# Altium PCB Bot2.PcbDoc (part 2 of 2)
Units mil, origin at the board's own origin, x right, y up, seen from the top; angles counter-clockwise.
Board outline 1717.4 x 2323.5 mil, 2 copper layers (Top1, Bottom2), stack 14.611 mil thick; 246 components, 15 nets, 1108 pads, 443 vias.
Unrouted connection lines stored in the file: 11.
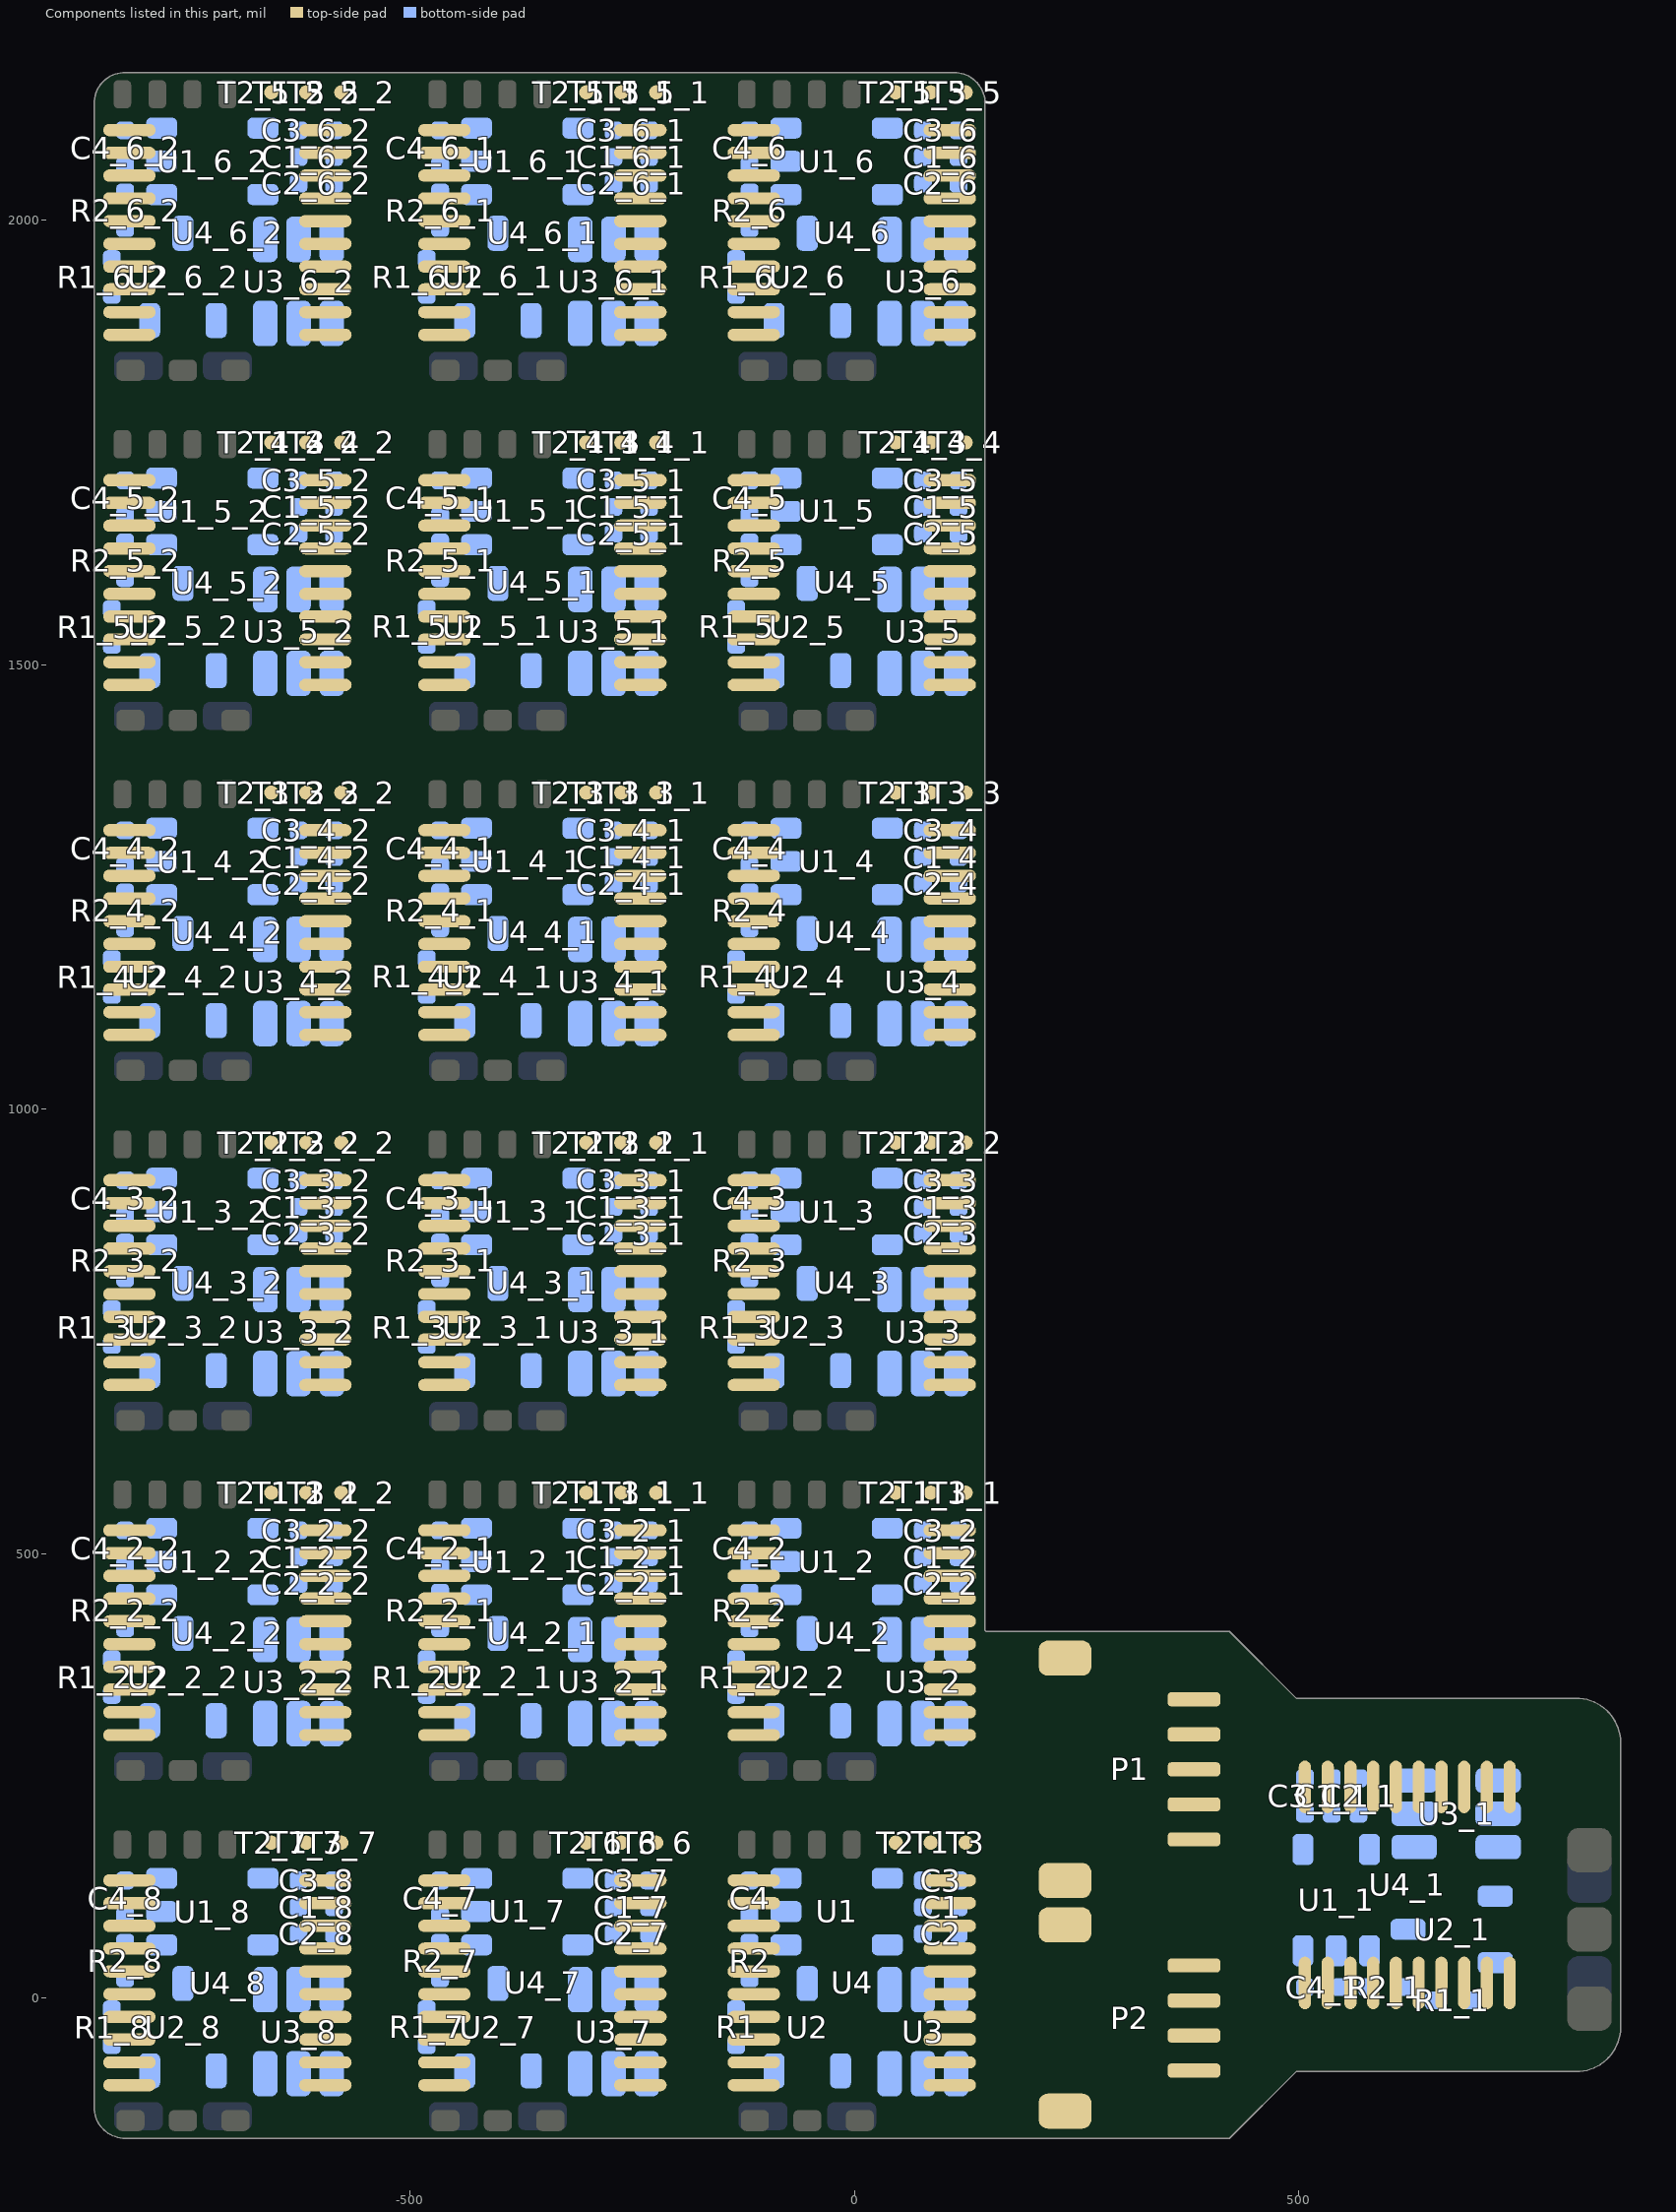
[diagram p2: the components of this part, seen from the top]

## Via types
v1: diameter 18, hole 10, Top1 to Bottom2, tented both sides, 443 vias

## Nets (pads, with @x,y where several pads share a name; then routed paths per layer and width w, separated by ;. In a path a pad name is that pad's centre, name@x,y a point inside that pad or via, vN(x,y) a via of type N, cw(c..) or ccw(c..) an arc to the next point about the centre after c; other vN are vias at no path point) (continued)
copper on no net: | length 48585.2
  Top1 w4: -744.92,173 -744.92,165.89 -726.55,147.52 -692.55,147.52 -636.55,91.52 -636.55,66.52 -622.55,52.52 -598.7,52.52 -595.31,55.91 ; -744.92,566.7 -744.92,559.59 -726.55,541.22 -692.55,541.22 -636.55,485.22 -636.55,460.22 -622.55,446.22 -598.7,446.22 -595.31,449.61 ; -744.92,960.4 -744.92,953.29 -726.55,934.92 -692.55,934.92 -636.55,878.92 -636.55,853.92 -622.55,839.92 -598.7,839.92 -595.31,843.31 ; -744.92,1354.1 -744.92,1346.99 -726.55,1328.62 -692.55,1328.62 -636.55,1272.62 -636.55,1247.62 -622.55,1233.62 -598.7,1233.62 -595.31,1237.01 ; -744.92,1747.8 -744.92,1740.69 -726.55,1722.32 -692.55,1722.32 -636.55,1666.32 -636.55,1641.32 -622.55,1627.32 -598.7,1627.32 -595.31,1630.71 ; -744.92,2141.5 -744.92,2134.39 -726.55,2116.02 -692.55,2116.02 -636.55,2060.02 -636.55,2035.02 -622.55,2021.02 -598.7,2021.02 -595.31,2024.41 ; -705.55,173 -614.05,81.5 -595.31,81.5 ; -705.55,566.7 -614.05,475.2 -595.31,475.2 ; -705.55,960.4 -614.05,868.9 -595.31,868.9 ; -705.55,1354.1 -614.05,1262.6 -595.31,1262.6 ; -705.55,1747.8 -614.05,1656.3 -595.31,1656.3 ; -705.55,2141.5 -614.05,2050 -595.31,2050 ; -656.18,175.01 -656.18,143.15 -620.12,107.09 -595.31,107.09 ; -656.18,568.71 -656.18,536.85 -620.12,500.79 -595.31,500.79 ; -656.18,962.41 -656.18,930.55 -620.12,894.49 -595.31,894.49 ; -656.18,1356.11 -656.18,1324.25 -620.12,1288.19 -595.31,1288.19 ; -656.18,1749.81 -656.18,1717.95 -620.12,1681.89 -595.31,1681.89 ; -656.18,2143.51 -656.18,2111.65 -620.12,2075.59 -595.31,2075.59 ; -616.81,175.01 -616.81,154.17 -595.31,132.68 ; -616.81,568.71 -616.81,547.87 -595.31,526.38 ; -616.81,962.41 -616.81,941.57 -595.31,920.08 ; -616.81,1356.11 -616.81,1335.28 -595.31,1313.78 ; -616.81,1749.81 -616.81,1728.98 -595.31,1707.48 ; -616.81,2143.51 -616.81,2122.68 -595.31,2101.18 ; -390.59,173 -390.59,165.89 -372.22,147.52 -338.22,147.52 -282.22,91.52 -282.22,66.52 -268.22,52.52 -244.37,52.52 -240.98,55.91 ; -390.59,566.7 -390.59,559.59 -372.22,541.22 -338.22,541.22 -282.22,485.22 -282.22,460.22 -268.22,446.22 -244.37,446.22 -240.98,449.61 ; -390.59,960.4 -390.59,953.29 -372.22,934.92 -338.22,934.92 -282.22,878.92 -282.22,853.92 -268.22,839.92 -244.37,839.92 -240.98,843.31 ; -390.59,1354.1 -390.59,1346.99 -372.22,1328.62 -338.22,1328.62 -282.22,1272.62 -282.22,1247.62 -268.22,1233.62 -244.37,1233.62 -240.98,1237.01 ; -390.59,1747.8 -390.59,1740.69 -372.22,1722.32 -338.22,1722.32 -282.22,1666.32 -282.22,1641.32 -268.22,1627.32 -244.37,1627.32 -240.98,1630.71 ; -390.59,2141.5 -390.59,2134.39 -372.22,2116.02 -338.22,2116.02 -282.22,2060.02 -282.22,2035.02 -268.22,2021.02 -244.37,2021.02 -240.98,2024.41 ; -351.22,173 -259.72,81.5 -240.98,81.5 ; -351.22,566.7 -259.72,475.2 -240.98,475.2 ; -351.22,960.4 -259.72,868.9 -240.98,868.9 ; -351.22,1354.1 -259.72,1262.6 -240.98,1262.6 ; -351.22,1747.8 -259.72,1656.3 -240.98,1656.3 ; -351.22,2141.5 -259.72,2050 -240.98,2050 ; -301.85,175.01 -301.85,143.15 -265.79,107.09 -240.98,107.09 ; -301.85,568.71 -301.85,536.85 -265.79,500.79 -240.98,500.79 ; -301.85,962.41 -301.85,930.55 -265.79,894.49 -240.98,894.49 ; -301.85,1356.11 -301.85,1324.25 -265.79,1288.19 -240.98,1288.19 ; -301.85,1749.81 -301.85,1717.95 -265.79,1681.89 -240.98,1681.89 ; -301.85,2143.51 -301.85,2111.65 -265.79,2075.59 -240.98,2075.59 ; -262.48,175.01 -262.48,154.17 -240.98,132.68 ; -262.48,568.71 -262.48,547.87 -240.98,526.38 ; -262.48,962.41 -262.48,941.57 -240.98,920.08 ; -262.48,1356.11 -262.48,1335.28 -240.98,1313.78 ; -262.48,1749.81 -262.48,1728.98 -240.98,1707.48 ; -262.48,2143.51 -262.48,2122.68 -240.98,2101.18 ; -42.48,173 -42.48,165.89 -24.11,147.52 9.89,147.52 65.89,91.52 65.89,66.52 79.89,52.52 103.74,52.52 107.13,55.91 ; -42.48,566.7 -42.48,559.59 -24.11,541.22 9.89,541.22 65.89,485.22 65.89,460.22 79.89,446.22 103.74,446.22 107.13,449.61 ; -42.48,960.4 -42.48,953.29 -24.11,934.92 9.89,934.92 65.89,878.92 65.89,853.92 79.89,839.92 103.74,839.92 107.13,843.31 ; -42.48,1354.1 -42.48,1346.99 -24.11,1328.62 9.89,1328.62 65.89,1272.62 65.89,1247.62 79.89,1233.62 103.74,1233.62 107.13,1237.01 ; -42.48,1747.8 -42.48,1740.69 -24.11,1722.32 9.89,1722.32 65.89,1666.32 65.89,1641.32 79.89,1627.32 103.74,1627.32 107.13,1630.71 ; -42.48,2141.5 -42.48,2134.39 -24.11,2116.02 9.89,2116.02 65.89,2060.02 65.89,2035.02 79.89,2021.02 103.74,2021.02 107.13,2024.41 ; -3.11,173 88.39,81.5 107.13,81.5 ; -3.11,566.7 88.39,475.2 107.13,475.2 ; -3.11,960.4 88.39,868.9 107.13,868.9 ; -3.11,1354.1 88.39,1262.6 107.13,1262.6 ; -3.11,1747.8 88.39,1656.3 107.13,1656.3 ; -3.11,2141.5 88.39,2050 107.13,2050 ; 46.26,175.01 46.26,143.15 82.32,107.09 107.13,107.09 ; 46.26,568.71 46.26,536.85 82.32,500.79 107.13,500.79 ; 46.26,962.41 46.26,930.55 82.32,894.49 107.13,894.49 ; 46.26,1356.11 46.26,1324.25 82.32,1288.19 107.13,1288.19 ; 46.26,1749.81 46.26,1717.95 82.32,1681.89 107.13,1681.89 ; 46.26,2143.51 46.26,2111.65 82.32,2075.59 107.13,2075.59 ; 85.63,175.01 85.63,154.17 107.13,132.68 ; 85.63,568.71 85.63,547.87 107.13,526.38 ; 85.63,962.41 85.63,941.57 107.13,920.08 ; 85.63,1356.11 85.63,1335.28 107.13,1313.78 ; 85.63,1749.81 85.63,1728.98 107.13,1707.48 ; 85.63,2143.51 85.63,2122.68 107.13,2101.18 ; 379.96,176.89 493.22,176.89 532.28,215.95 532.28,237.76 ; 381.85,-2.48 401.85,-2.48 424.85,20.52 424.85,95.52 447.85,118.52 469.85,118.52 547.85,196.52 572.85,196.52 586.85,210.52 586.85,234.37 583.46,237.76 ; 381.85,36.89 381.85,82.52 426.85,127.52 466.37,127.52 557.87,219.02 557.87,237.76 ; 381.85,218.15 407.22,218.15 423.85,201.52 491.85,201.52 506.69,216.36 506.69,237.76 ; v1(685.83,-41.46) 685.83,17.28 ; v1(711.42,-27.05) 711.42,17.28
  Top1 w5: v1(-592.55,159.52) -577.44,174.63 -577.44,175.01 ; v1(-592.55,553.22) -577.44,568.33 -577.44,568.71 ; v1(-592.55,946.92) -577.44,962.03 -577.44,962.41 ; v1(-592.55,1340.62) -577.44,1355.73 -577.44,1356.11 ; v1(-592.55,1734.32) -577.44,1749.43 -577.44,1749.81 ; v1(-592.55,2128.02) -577.44,2143.13 -577.44,2143.51 ; v1(-238.22,159.52) -223.11,174.63 -223.11,175.01 ; v1(-238.22,553.22) -223.11,568.33 -223.11,568.71 ; v1(-238.22,946.92) -223.11,962.03 -223.11,962.41 ; v1(-238.22,1340.62) -223.11,1355.73 -223.11,1356.11 ; v1(-238.22,1734.32) -223.11,1749.43 -223.11,1749.81 ; v1(-238.22,2128.02) -223.11,2143.13 -223.11,2143.51 ; v1(109.89,159.52) 125,174.63 125,175.01 ; v1(109.89,553.22) 125,568.33 125,568.71 ; v1(109.89,946.92) 125,962.03 125,962.41 ; v1(109.89,1340.62) 125,1355.73 125,1356.11 ; v1(109.89,1734.32) 125,1749.43 125,1749.81 ; v1(109.89,2128.02) 125,2143.13 125,2143.51
  Top1 w10: -815.79,-136.3 -815.79,-97.64 ; -815.79,257.4 -815.79,296.06 ; -815.79,651.1 -815.79,689.76 ; -815.79,1044.8 -815.79,1083.46 ; -815.79,1438.5 -815.79,1477.17 ; -815.79,1832.2 -815.79,1870.87 ; v1(-765.55,-41.48) -765.55,-72.48 -747.55,-90.48 ; v1(-765.55,352.22) -765.55,321.22 -747.55,303.22 ; v1(-765.55,745.92) -765.55,714.92 -747.55,696.92 ; v1(-765.55,1139.62) -765.55,1108.62 -747.55,1090.62 ; v1(-765.55,1533.32) -765.55,1502.32 -747.55,1484.32 ; v1(-765.55,1927.02) -765.55,1896.02 -747.55,1878.02 ; -755.55,-137.48 -755.55,-98.48 -747.55,-90.48 ; -755.55,256.22 -755.55,295.22 -747.55,303.22 ; -755.55,649.92 -755.55,688.92 -747.55,696.92 ; -755.55,1043.62 -755.55,1082.62 -747.55,1090.62 ; -755.55,1437.32 -755.55,1476.32 -747.55,1484.32 ; -755.55,1831.02 -755.55,1870.02 -747.55,1878.02 ; v1(-720.55,-90.48) -747.55,-90.48 ; v1(-720.55,303.22) -747.55,303.22 ; v1(-720.55,696.92) -747.55,696.92 ; v1(-720.55,1090.62) -747.55,1090.62 ; v1(-720.55,1484.32) -747.55,1484.32 ; v1(-720.55,1878.02) -747.55,1878.02 ; v1(-649.55,-37.48) -640.57,-46.46 -595.31,-46.46 ; v1(-649.55,356.22) -640.57,347.24 -595.31,347.24 ; v1(-649.55,749.92) -640.57,740.94 -595.31,740.94 ; v1(-649.55,1143.62) -640.57,1134.65 -595.31,1134.65 ; v1(-649.55,1537.32) -640.57,1528.35 -595.31,1528.35 ; v1(-649.55,1931.02) -640.57,1922.05 -595.31,1922.05 ; -461.46,-136.3 -461.46,-97.64 ; -461.46,257.4 -461.46,296.06 ; -461.46,651.1 -461.46,689.76 ; -461.46,1044.8 -461.46,1083.46 ; -461.46,1438.5 -461.46,1477.17 ; -461.46,1832.2 -461.46,1870.87 ; v1(-411.22,-41.48) -411.22,-72.48 -393.22,-90.48 ; v1(-411.22,352.22) -411.22,321.22 -393.22,303.22 ; v1(-411.22,745.92) -411.22,714.92 -393.22,696.92 ; v1(-411.22,1139.62) -411.22,1108.62 -393.22,1090.62 ; v1(-411.22,1533.32) -411.22,1502.32 -393.22,1484.32 ; v1(-411.22,1927.02) -411.22,1896.02 -393.22,1878.02 ; -401.22,-137.48 -401.22,-98.48 -393.22,-90.48 ; -401.22,256.22 -401.22,295.22 -393.22,303.22 ; -401.22,649.92 -401.22,688.92 -393.22,696.92 ; -401.22,1043.62 -401.22,1082.62 -393.22,1090.62 ; -401.22,1437.32 -401.22,1476.32 -393.22,1484.32 ; -401.22,1831.02 -401.22,1870.02 -393.22,1878.02 ; v1(-366.22,-90.48) -393.22,-90.48 ; v1(-366.22,303.22) -393.22,303.22 ; v1(-366.22,696.92) -393.22,696.92 ; v1(-366.22,1090.62) -393.22,1090.62 ; v1(-366.22,1484.32) -393.22,1484.32 ; v1(-366.22,1878.02) -393.22,1878.02 ; v1(-295.22,-37.48) -286.24,-46.46 -240.98,-46.46 ; v1(-295.22,356.22) -286.24,347.24 -240.98,347.24 ; v1(-295.22,749.92) -286.24,740.94 -240.98,740.94 ; v1(-295.22,1143.62) -286.24,1134.65 -240.98,1134.65 ; v1(-295.22,1537.32) -286.24,1528.35 -240.98,1528.35 ; v1(-295.22,1931.02) -286.24,1922.05 -240.98,1922.05 ; -113.35,-136.3 -113.35,-97.64 ; -113.35,257.4 -113.35,296.06 ; -113.35,651.1 -113.35,689.76 ; -113.35,1044.8 -113.35,1083.46 ; -113.35,1438.5 -113.35,1477.17 ; -113.35,1832.2 -113.35,1870.87 ; v1(-63.11,-41.48) -63.11,-72.48 -45.11,-90.48 ; v1(-63.11,352.22) -63.11,321.22 -45.11,303.22 ; v1(-63.11,745.92) -63.11,714.92 -45.11,696.92 ; v1(-63.11,1139.62) -63.11,1108.62 -45.11,1090.62 ; v1(-63.11,1533.32) -63.11,1502.32 -45.11,1484.32 ; v1(-63.11,1927.02) -63.11,1896.02 -45.11,1878.02 ; -53.11,-137.48 -53.11,-98.48 -45.11,-90.48 ; -53.11,256.22 -53.11,295.22 -45.11,303.22 ; -53.11,649.92 -53.11,688.92 -45.11,696.92 ; -53.11,1043.62 -53.11,1082.62 -45.11,1090.62 ; -53.11,1437.32 -53.11,1476.32 -45.11,1484.32 ; -53.11,1831.02 -53.11,1870.02 -45.11,1878.02 ; v1(-18.11,-90.48) -45.11,-90.48 ; v1(-18.11,303.22) -45.11,303.22 ; v1(-18.11,696.92) -45.11,696.92 ; v1(-18.11,1090.62) -45.11,1090.62 ; v1(-18.11,1484.32) -45.11,1484.32 ; v1(-18.11,1878.02) -45.11,1878.02 ; v1(52.89,-37.48) 61.87,-46.46 107.13,-46.46 ; v1(52.89,356.22) 61.87,347.24 107.13,347.24 ; v1(52.89,749.92) 61.87,740.94 107.13,740.94 ; v1(52.89,1143.62) 61.87,1134.65 107.13,1134.65 ; v1(52.89,1537.32) 61.87,1528.35 107.13,1528.35 ; v1(52.89,1931.02) 61.87,1922.05 107.13,1922.05 ; v1(676.85,183.52) 685.83,192.5 685.83,237.76 ; v1(680.85,67.52) 711.85,67.52 729.85,85.52 ; v1(729.85,112.52) 729.85,85.52 ; 737.01,17.28 798.03,17.28 826.85,-11.54 ; 826.85,77.52 737.85,77.52 729.85,85.52
  Top1 w15: -784.29,173 -784.29,160.26 v1(-764.55,140.52) -712.55,88.52 -712.55,-43.48 v1(-623.55,-132.48) v1(-595.55,-132.48) ; -784.29,566.7 -784.29,553.96 v1(-764.55,534.22) -712.55,482.22 -712.55,350.22 v1(-623.55,261.22) v1(-595.55,261.22) ; -784.29,960.4 -784.29,947.66 v1(-764.55,927.92) -712.55,875.92 -712.55,743.92 v1(-623.55,654.92) v1(-595.55,654.92) ; -784.29,1354.1 -784.29,1341.36 v1(-764.55,1321.62) -712.55,1269.62 -712.55,1137.62 v1(-623.55,1048.62) v1(-595.55,1048.62) ; -784.29,1747.8 -784.29,1735.06 v1(-764.55,1715.32) -712.55,1663.32 -712.55,1531.32 v1(-623.55,1442.32) v1(-595.55,1442.32) ; -784.29,2141.5 -784.29,2128.76 v1(-764.55,2109.02) -712.55,2057.02 -712.55,1925.02 v1(-623.55,1836.02) v1(-595.55,1836.02) ; v1(-664.55,59.52) -635.35,30.32 -595.31,30.32 ; v1(-664.55,453.22) -635.35,424.02 -595.31,424.02 ; v1(-664.55,846.92) -635.35,817.72 -595.31,817.72 ; v1(-664.55,1240.62) -635.35,1211.42 -595.31,1211.42 ; v1(-664.55,1634.32) -635.35,1605.12 -595.31,1605.12 ; v1(-664.55,2028.02) -635.35,1998.82 -595.31,1998.82 ; -429.96,173 -429.96,160.26 v1(-410.22,140.52) -358.22,88.52 -358.22,-43.48 v1(-269.22,-132.48) v1(-241.22,-132.48) ; -429.96,566.7 -429.96,553.96 v1(-410.22,534.22) -358.22,482.22 -358.22,350.22 v1(-269.22,261.22) v1(-241.22,261.22) ; -429.96,960.4 -429.96,947.66 v1(-410.22,927.92) -358.22,875.92 -358.22,743.92 v1(-269.22,654.92) v1(-241.22,654.92) ; -429.96,1354.1 -429.96,1341.36 v1(-410.22,1321.62) -358.22,1269.62 -358.22,1137.62 v1(-269.22,1048.62) v1(-241.22,1048.62) ; -429.96,1747.8 -429.96,1735.06 v1(-410.22,1715.32) -358.22,1663.32 -358.22,1531.32 v1(-269.22,1442.32) v1(-241.22,1442.32) ; -429.96,2141.5 -429.96,2128.76 v1(-410.22,2109.02) -358.22,2057.02 -358.22,1925.02 v1(-269.22,1836.02) v1(-241.22,1836.02) ; v1(-310.22,59.52) -281.02,30.32 -240.98,30.32 ; v1(-310.22,453.22) -281.02,424.02 -240.98,424.02 ; v1(-310.22,846.92) -281.02,817.72 -240.98,817.72 ; v1(-310.22,1240.62) -281.02,1211.42 -240.98,1211.42 ; v1(-310.22,1634.32) -281.02,1605.12 -240.98,1605.12 ; v1(-310.22,2028.02) -281.02,1998.82 -240.98,1998.82 ; -81.85,173 -81.85,160.26 v1(-62.11,140.52) -10.11,88.52 -10.11,-43.48 v1(78.89,-132.48) v1(106.89,-132.48) ; -81.85,566.7 -81.85,553.96 v1(-62.11,534.22) -10.11,482.22 -10.11,350.22 v1(78.89,261.22) v1(106.89,261.22) ; -81.85,960.4 -81.85,947.66 v1(-62.11,927.92) -10.11,875.92 -10.11,743.92 v1(78.89,654.92) v1(106.89,654.92) ; -81.85,1354.1 -81.85,1341.36 v1(-62.11,1321.62) -10.11,1269.62 -10.11,1137.62 v1(78.89,1048.62) v1(106.89,1048.62) ; -81.85,1747.8 -81.85,1735.06 v1(-62.11,1715.32) -10.11,1663.32 -10.11,1531.32 v1(78.89,1442.32) v1(106.89,1442.32) ; -81.85,2141.5 -81.85,2128.76 v1(-62.11,2109.02) -10.11,2057.02 -10.11,1925.02 v1(78.89,1836.02) v1(106.89,1836.02) ; v1(37.89,59.52) 67.09,30.32 107.13,30.32 ; v1(37.89,453.22) 67.09,424.02 107.13,424.02 ; v1(37.89,846.92) 67.09,817.72 107.13,817.72 ; v1(37.89,1240.62) 67.09,1211.42 107.13,1211.42 ; v1(37.89,1634.32) 67.09,1605.12 107.13,1605.12 ; v1(37.89,2028.02) 67.09,1998.82 107.13,1998.82 ; 381.85,-41.85 409.48,-41.85 444.85,-6.48 444.85,12.52 v1(480.85,48.52) ; v1@479.11,48.78 v1(498.85,68.52) 550.85,120.52 682.85,120.52 v1(771.85,209.52) v1(771.85,237.52) ; v1(579.85,168.52) 609.06,197.72 609.06,237.76
  Bottom2 w4: v1(394.85,296.52) 424.85,266.52 424.85,-3.17 463.14,-41.46 v1(685.83,-41.46) ; v1(394.85,337.52) 369.85,312.52 369.85,286.52 416.85,239.52 416.85,-6.48 472.85,-62.48 696.85,-62.48 711.42,-47.91 v1(711.42,-27.05)
  Bottom2 w10: -835.55,-52.48 -806.5,-81.54 -792.95,-81.54 -792.95,-68.88 v1(-765.55,-41.48) ; -835.55,341.22 -806.5,312.17 -792.95,312.17 -792.95,324.82 v1(-765.55,352.22) ; -835.55,734.92 -806.5,705.87 -792.95,705.87 -792.95,718.52 v1(-765.55,745.92) ; -835.55,1128.62 -806.5,1099.57 -792.95,1099.57 -792.95,1112.22 v1(-765.55,1139.62) ; -835.55,1522.32 -806.5,1493.27 -792.95,1493.27 -792.95,1505.92 v1(-765.55,1533.32) ; -835.55,1916.02 -806.5,1886.97 -792.95,1886.97 -792.95,1899.62 v1(-765.55,1927.02) ; v1(-649.55,-37.48) -622.55,-37.48 -593.15,-8.08 -593.15,9.76 ; v1(-649.55,356.22) -622.55,356.22 -593.15,385.62 -593.15,403.46 ; v1(-649.55,749.92) -622.55,749.92 -593.15,779.32 -593.15,797.17 ; v1(-649.55,1143.62) -622.55,1143.62 -593.15,1173.02 -593.15,1190.87 ; v1(-649.55,1537.32) -622.55,1537.32 -593.15,1566.72 -593.15,1584.57 ; v1(-649.55,1931.02) -622.55,1931.02 -593.15,1960.43 -593.15,1978.27 ; -481.22,-52.48 -452.17,-81.54 -438.62,-81.54 -438.62,-68.88 v1(-411.22,-41.48) ; -481.22,341.22 -452.17,312.17 -438.62,312.17 -438.62,324.82 v1(-411.22,352.22) ; -481.22,734.92 -452.17,705.87 -438.62,705.87 -438.62,718.52 v1(-411.22,745.92) ; -481.22,1128.62 -452.17,1099.57 -438.62,1099.57 -438.62,1112.22 v1(-411.22,1139.62) ; -481.22,1522.32 -452.17,1493.27 -438.62,1493.27 -438.62,1505.92 v1(-411.22,1533.32) ; -481.22,1916.02 -452.17,1886.97 -438.62,1886.97 -438.62,1899.62 v1(-411.22,1927.02) ; v1(-295.22,-37.48) -268.22,-37.48 -238.82,-8.08 -238.82,9.76 ; v1(-295.22,356.22) -268.22,356.22 -238.82,385.62 -238.82,403.46 ; v1(-295.22,749.92) -268.22,749.92 -238.82,779.32 -238.82,797.17 ; v1(-295.22,1143.62) -268.22,1143.62 -238.82,1173.02 -238.82,1190.87 ; v1(-295.22,1537.32) -268.22,1537.32 -238.82,1566.72 -238.82,1584.57 ; v1(-295.22,1931.02) -268.22,1931.02 -238.82,1960.43 -238.82,1978.27 ; -133.11,-52.48 -104.06,-81.54 -90.51,-81.54 -90.51,-68.88 v1(-63.11,-41.48) ; -133.11,341.22 -104.06,312.17 -90.51,312.17 -90.51,324.82 v1(-63.11,352.22) ; -133.11,734.92 -104.06,705.87 -90.51,705.87 -90.51,718.52 v1(-63.11,745.92) ; -133.11,1128.62 -104.06,1099.57 -90.51,1099.57 -90.51,1112.22 v1(-63.11,1139.62) ; -133.11,1522.32 -104.06,1493.27 -90.51,1493.27 -90.51,1505.92 v1(-63.11,1533.32) ; -133.11,1916.02 -104.06,1886.97 -90.51,1886.97 -90.51,1899.62 v1(-63.11,1927.02) ; v1(52.89,-37.48) 79.89,-37.48 109.29,-8.08 109.29,9.76 ; v1(52.89,356.22) 79.89,356.22 109.29,385.62 109.29,403.46 ; v1(52.89,749.92) 79.89,749.92 109.29,779.32 109.29,797.17 ; v1(52.89,1143.62) 79.89,1143.62 109.29,1173.02 109.29,1190.87 ; v1(52.89,1537.32) 79.89,1537.32 109.29,1566.72 109.29,1584.57 ; v1(52.89,1931.02) 79.89,1931.02 109.29,1960.43 109.29,1978.27 ; 629.61,239.92 647.45,239.92 676.85,210.52 v1(676.85,183.52) ; v1(680.85,67.52) 708.25,40.12 720.91,40.12 720.91,26.57 691.85,-2.48
  Bottom2 w15: -820.55,62.52 -820.55,92.52 ; -820.55,456.22 -820.55,486.22 ; -820.55,849.92 -820.55,879.92 ; -820.55,1243.62 -820.55,1273.62 ; -820.55,1637.32 -820.55,1667.32 ; -820.55,2031.02 -820.55,2061.02 ; v1(-808.55,30.52) -812.55,30.52 -820.55,22.52 -835.55,7.52 -835.55,-12.48 -830.55,-17.48 -739.55,-17.48 -703.55,18.52 -703.55,44.52 -687.95,60.12 -665.61,60.12 -637.95,60.12 -625.55,72.52 -625.55,102.52 ; v1(-808.55,424.22) -812.55,424.22 -820.55,416.22 -835.55,401.22 -835.55,381.22 -830.55,376.22 -739.55,376.22 -703.55,412.22 -703.55,438.22 -687.95,453.82 -665.61,453.82 -637.95,453.82 -625.55,466.22 -625.55,496.22 ; v1(-808.55,817.92) -812.55,817.92 -820.55,809.92 -835.55,794.92 -835.55,774.92 -830.55,769.92 -739.55,769.92 -703.55,805.92 -703.55,831.92 -687.95,847.52 -665.61,847.52 -637.95,847.52 -625.55,859.92 -625.55,889.92 ; v1(-808.55,1211.62) -812.55,1211.62 -820.55,1203.62 -835.55,1188.62 -835.55,1168.62 -830.55,1163.62 -739.55,1163.62 -703.55,1199.62 -703.55,1225.62 -687.95,1241.22 -665.61,1241.22 -637.95,1241.22 -625.55,1253.62 -625.55,1283.62 ; v1(-808.55,1605.32) -812.55,1605.32 -820.55,1597.32 -835.55,1582.32 -835.55,1562.32 -830.55,1557.32 -739.55,1557.32 -703.55,1593.32 -703.55,1619.32 -687.95,1634.92 -665.61,1634.92 -637.95,1634.92 -625.55,1647.32 -625.55,1677.32 ; v1(-808.55,1999.02) -812.55,1999.02 -820.55,1991.02 -835.55,1976.02 -835.55,1956.02 -830.55,1951.02 -739.55,1951.02 -703.55,1987.02 -703.55,2013.02 -687.95,2028.62 -665.61,2028.62 -637.95,2028.62 -625.55,2041.02 -625.55,2071.02 ; -805.55,-132.48 -771.55,-132.48 -749.55,-110.48 -749.55,-60.48 -720.55,-31.48 -709.2,-31.48 -667.95,9.76 ; -805.55,261.22 -771.55,261.22 -749.55,283.22 -749.55,333.22 -720.55,362.22 -709.2,362.22 -667.95,403.46 ; -805.55,654.92 -771.55,654.92 -749.55,676.92 -749.55,726.92 -720.55,755.92 -709.2,755.92 -667.95,797.17 ; -805.55,1048.62 -771.55,1048.62 -749.55,1070.62 -749.55,1120.62 -720.55,1149.62 -709.2,1149.62 -667.95,1190.87 ; -805.55,1442.32 -771.55,1442.32 -749.55,1464.32 -749.55,1514.32 -720.55,1543.32 -709.2,1543.32 -667.95,1584.57 ; -805.55,1836.02 -771.55,1836.02 -749.55,1858.02 -749.55,1908.02 -720.55,1937.02 -709.2,1937.02 -667.95,1978.27 ; -779.61,60.12 -738.95,60.12 -724.55,74.52 -724.55,108.52 -756.55,140.52 v1(-764.55,140.52) -782.55,158.52 v1(-784.55,158.52) -784.55,139.87 -779.61,134.92 ; -779.61,453.82 -738.95,453.82 -724.55,468.22 -724.55,502.22 -756.55,534.22 v1(-764.55,534.22) -782.55,552.22 v1(-784.55,552.22) -784.55,533.57 -779.61,528.62 ; -779.61,847.52 -738.95,847.52 -724.55,861.92 -724.55,895.92 -756.55,927.92 v1(-764.55,927.92) -782.55,945.92 v1(-784.55,945.92) -784.55,927.27 -779.61,922.32 ; -779.61,1241.22 -738.95,1241.22 -724.55,1255.62 -724.55,1289.62 -756.55,1321.62 v1(-764.55,1321.62) -782.55,1339.62 v1(-784.55,1339.62) -784.55,1320.97 -779.61,1316.02 ; -779.61,1634.92 -738.95,1634.92 -724.55,1649.32 -724.55,1683.32 -756.55,1715.32 v1(-764.55,1715.32) -782.55,1733.32 v1(-784.55,1733.32) -784.55,1714.67 -779.61,1709.72 ; -779.61,2028.62 -738.95,2028.62 -724.55,2043.02 -724.55,2077.02 -756.55,2109.02 v1(-764.55,2109.02) -782.55,2127.02 v1(-784.55,2127.02) -784.55,2108.37 -779.61,2103.43 ; -705.55,-132.48 -667.95,-94.88 -667.95,-84.72 ; -705.55,261.22 -667.95,298.82 -667.95,308.98 ; -705.55,654.92 -667.95,692.52 -667.95,702.68 ; -705.55,1048.62 -667.95,1086.22 -667.95,1096.38 ; -705.55,1442.32 -667.95,1479.92 -667.95,1490.08 ; -705.55,1836.02 -667.95,1873.62 -667.95,1883.78 ; -665.61,134.92 -627.95,134.92 ; -665.61,528.62 -627.95,528.62 ; -665.61,922.32 -627.95,922.32 ; -665.61,1316.02 -627.95,1316.02 ; -665.61,1709.72 -627.95,1709.72 ; -665.61,2103.43 -627.95,2103.43 ; -630.55,-84.72 -630.55,-125.48 v1(-623.55,-132.48) v1(-595.55,-132.48) ; -630.55,308.98 -630.55,268.22 v1(-623.55,261.22) v1(-595.55,261.22) ; -630.55,702.68 -630.55,661.92 v1(-623.55,654.92) v1(-595.55,654.92) ; -630.55,1096.38 -630.55,1055.62 v1(-623.55,1048.62) v1(-595.55,1048.62) ; -630.55,1490.08 -630.55,1449.32 v1(-623.55,1442.32) v1(-595.55,1442.32) ; -630.55,1883.78 -630.55,1843.02 v1(-623.55,1836.02) v1(-595.55,1836.02) ; -466.22,62.52 -466.22,92.52 ; -466.22,456.22 -466.22,486.22 ; -466.22,849.92 -466.22,879.92 ; -466.22,1243.62 -466.22,1273.62 ; -466.22,1637.32 -466.22,1667.32 ; -466.22,2031.02 -466.22,2061.02 ; v1(-454.22,30.52) -458.22,30.52 -466.22,22.52 -481.22,7.52 -481.22,-12.48 -476.22,-17.48 -385.22,-17.48 -349.22,18.52 -349.22,44.52 -333.62,60.12 -311.28,60.12 -283.62,60.12 -271.22,72.52 -271.22,102.52 ; v1(-454.22,424.22) -458.22,424.22 -466.22,416.22 -481.22,401.22 -481.22,381.22 -476.22,376.22 -385.22,376.22 -349.22,412.22 -349.22,438.22 -333.62,453.82 -311.28,453.82 -283.62,453.82 -271.22,466.22 -271.22,496.22 ; v1(-454.22,817.92) -458.22,817.92 -466.22,809.92 -481.22,794.92 -481.22,774.92 -476.22,769.92 -385.22,769.92 -349.22,805.92 -349.22,831.92 -333.62,847.52 -311.28,847.52 -283.62,847.52 -271.22,859.92 -271.22,889.92 ; v1(-454.22,1211.62) -458.22,1211.62 -466.22,1203.62 -481.22,1188.62 -481.22,1168.62 -476.22,1163.62 -385.22,1163.62 -349.22,1199.62 -349.22,1225.62 -333.62,1241.22 -311.28,1241.22 -283.62,1241.22 -271.22,1253.62 -271.22,1283.62 ; v1(-454.22,1605.32) -458.22,1605.32 -466.22,1597.32 -481.22,1582.32 -481.22,1562.32 -476.22,1557.32 -385.22,1557.32 -349.22,1593.32 -349.22,1619.32 -333.62,1634.92 -311.28,1634.92 -283.62,1634.92 -271.22,1647.32 -271.22,1677.32 ; v1(-454.22,1999.02) -458.22,1999.02 -466.22,1991.02 -481.22,1976.02 -481.22,1956.02 -476.22,1951.02 -385.22,1951.02 -349.22,1987.02 -349.22,2013.02 -333.62,2028.62 -311.28,2028.62 -283.62,2028.62 -271.22,2041.02 -271.22,2071.02 ; -451.22,-132.48 -417.22,-132.48 -395.22,-110.48 -395.22,-60.48 -366.22,-31.48 -354.87,-31.48 -313.62,9.76 ; -451.22,261.22 -417.22,261.22 -395.22,283.22 -395.22,333.22 -366.22,362.22 -354.87,362.22 -313.62,403.46 ; -451.22,654.92 -417.22,654.92 -395.22,676.92 -395.22,726.92 -366.22,755.92 -354.87,755.92 -313.62,797.17 ; -451.22,1048.62 -417.22,1048.62 -395.22,1070.62 -395.22,1120.62 -366.22,1149.62 -354.87,1149.62 -313.62,1190.87 ; -451.22,1442.32 -417.22,1442.32 -395.22,1464.32 -395.22,1514.32 -366.22,1543.32 -354.87,1543.32 -313.62,1584.57 ; -451.22,1836.02 -417.22,1836.02 -395.22,1858.02 -395.22,1908.02 -366.22,1937.02 -354.87,1937.02 -313.62,1978.27 ; -425.28,60.12 -384.62,60.12 -370.22,74.52 -370.22,108.52 -402.22,140.52 v1(-410.22,140.52) -428.22,158.52 v1(-430.22,158.52) -430.22,139.87 -425.28,134.92 ; -425.28,453.82 -384.62,453.82 -370.22,468.22 -370.22,502.22 -402.22,534.22 v1(-410.22,534.22) -428.22,552.22 v1(-430.22,552.22) -430.22,533.57 -425.28,528.62 ; -425.28,847.52 -384.62,847.52 -370.22,861.92 -370.22,895.92 -402.22,927.92 v1(-410.22,927.92) -428.22,945.92 v1(-430.22,945.92) -430.22,927.27 -425.28,922.32 ; -425.28,1241.22 -384.62,1241.22 -370.22,1255.62 -370.22,1289.62 -402.22,1321.62 v1(-410.22,1321.62) -428.22,1339.62 v1(-430.22,1339.62) -430.22,1320.97 -425.28,1316.02 ; -425.28,1634.92 -384.62,1634.92 -370.22,1649.32 -370.22,1683.32 -402.22,1715.32 v1(-410.22,1715.32) -428.22,1733.32 v1(-430.22,1733.32) -430.22,1714.67 -425.28,1709.72 ; -425.28,2028.62 -384.62,2028.62 -370.22,2043.02 -370.22,2077.02 -402.22,2109.02 v1(-410.22,2109.02) -428.22,2127.02 v1(-430.22,2127.02) -430.22,2108.37 -425.28,2103.43 ; -351.22,-132.48 -313.62,-94.88 -313.62,-84.72 ; -351.22,261.22 -313.62,298.82 -313.62,308.98 ; -351.22,654.92 -313.62,692.52 -313.62,702.68 ; -351.22,1048.62 -313.62,1086.22 -313.62,1096.38 ; -351.22,1442.32 -313.62,1479.92 -313.62,1490.08 ; -351.22,1836.02 -313.62,1873.62 -313.62,1883.78 ; -311.28,134.92 -273.62,134.92 ; -311.28,528.62 -273.62,528.62 ; -311.28,922.32 -273.62,922.32 ; -311.28,1316.02 -273.62,1316.02 ; -311.28,1709.72 -273.62,1709.72 ; -311.28,2103.43 -273.62,2103.43 ; -276.22,-84.72 -276.22,-125.48 v1(-269.22,-132.48) v1(-241.22,-132.48) ; -276.22,308.98 -276.22,268.22 v1(-269.22,261.22) v1(-241.22,261.22) ; -276.22,702.68 -276.22,661.92 v1(-269.22,654.92) v1(-241.22,654.92) ; -276.22,1096.38 -276.22,1055.62 v1(-269.22,1048.62) v1(-241.22,1048.62) ; -276.22,1490.08 -276.22,1449.32 v1(-269.22,1442.32) v1(-241.22,1442.32) ; -276.22,1883.78 -276.22,1843.02 v1(-269.22,1836.02) v1(-241.22,1836.02) ; -118.11,62.52 -118.11,92.52 ; -118.11,456.22 -118.11,486.22 ; -118.11,849.92 -118.11,879.92 ; -118.11,1243.62 -118.11,1273.62 ; -118.11,1637.32 -118.11,1667.32 ; -118.11,2031.02 -118.11,2061.02 ; v1(-106.11,30.52) -110.11,30.52 -118.11,22.52 -133.11,7.52 -133.11,-12.48 -128.11,-17.48 -37.11,-17.48 -1.11,18.52 -1.11,44.52 14.49,60.12 36.83,60.12 64.49,60.12 76.89,72.52 76.89,102.52 ; v1(-106.11,424.22) -110.11,424.22 -118.11,416.22 -133.11,401.22 -133.11,381.22 -128.11,376.22 -37.11,376.22 -1.11,412.22 -1.11,438.22 14.49,453.82 36.83,453.82 64.49,453.82 76.89,466.22 76.89,496.22 ; v1(-106.11,817.92) -110.11,817.92 -118.11,809.92 -133.11,794.92 -133.11,774.92 -128.11,769.92 -37.11,769.92 -1.11,805.92 -1.11,831.92 14.49,847.52 36.83,847.52 64.49,847.52 76.89,859.92 76.89,889.92 ; v1(-106.11,1211.62) -110.11,1211.62 -118.11,1203.62 -133.11,1188.62 -133.11,1168.62 -128.11,1163.62 -37.11,1163.62 -1.11,1199.62 -1.11,1225.62 14.49,1241.22 36.83,1241.22 64.49,1241.22 76.89,1253.62 76.89,1283.62 ; v1(-106.11,1605.32) -110.11,1605.32 -118.11,1597.32 -133.11,1582.32 -133.11,1562.32 -128.11,1557.32 -37.11,1557.32 -1.11,1593.32 -1.11,1619.32 14.49,1634.92 36.83,1634.92 64.49,1634.92 76.89,1647.32 76.89,1677.32 ; v1(-106.11,1999.02) -110.11,1999.02 -118.11,1991.02 -133.11,1976.02 -133.11,1956.02 -128.11,1951.02 -37.11,1951.02 -1.11,1987.02 -1.11,2013.02 14.49,2028.62 36.83,2028.62 64.49,2028.62 76.89,2041.02 76.89,2071.02 ; -103.11,-132.48 -69.11,-132.48 -47.11,-110.48 -47.11,-60.48 -18.11,-31.48 -6.76,-31.48 34.49,9.76 ; -103.11,261.22 -69.11,261.22 -47.11,283.22 -47.11,333.22 -18.11,362.22 -6.76,362.22 34.49,403.46 ; -103.11,654.92 -69.11,654.92 -47.11,676.92 -47.11,726.92 -18.11,755.92 -6.76,755.92 34.49,797.17 ; -103.11,1048.62 -69.11,1048.62 -47.11,1070.62 -47.11,1120.62 -18.11,1149.62 -6.76,1149.62 34.49,1190.87 ; -103.11,1442.32 -69.11,1442.32 -47.11,1464.32 -47.11,1514.32 -18.11,1543.32 -6.76,1543.32 34.49,1584.57 ; -103.11,1836.02 -69.11,1836.02 -47.11,1858.02 -47.11,1908.02 -18.11,1937.02 -6.76,1937.02 34.49,1978.27 ; -77.17,60.12 -36.51,60.12 -22.11,74.52 -22.11,108.52 -54.11,140.52 v1(-62.11,140.52) -80.11,158.52 v1(-82.11,158.52) -82.11,139.87 -77.17,134.92 ; -77.17,453.82 -36.51,453.82 -22.11,468.22 -22.11,502.22 -54.11,534.22 v1(-62.11,534.22) -80.11,552.22 v1(-82.11,552.22) -82.11,533.57 -77.17,528.62 ; -77.17,847.52 -36.51,847.52 -22.11,861.92 -22.11,895.92 -54.11,927.92 v1(-62.11,927.92) -80.11,945.92 v1(-82.11,945.92) -82.11,927.27 -77.17,922.32 ; -77.17,1241.22 -36.51,1241.22 -22.11,1255.62 -22.11,1289.62 -54.11,1321.62 v1(-62.11,1321.62) -80.11,1339.62 v1(-82.11,1339.62) -82.11,1320.97 -77.17,1316.02 ; -77.17,1634.92 -36.51,1634.92 -22.11,1649.32 -22.11,1683.32 -54.11,1715.32 v1(-62.11,1715.32) -80.11,1733.32 v1(-82.11,1733.32) -82.11,1714.67 -77.17,1709.72 ; -77.17,2028.62 -36.51,2028.62 -22.11,2043.02 -22.11,2077.02 -54.11,2109.02 v1(-62.11,2109.02) -80.11,2127.02 v1(-82.11,2127.02) -82.11,2108.37 -77.17,2103.43 ; -3.11,-132.48 34.49,-94.88 34.49,-84.72 ; -3.11,261.22 34.49,298.82 34.49,308.98 ; -3.11,654.92 34.49,692.52 34.49,702.68 ; -3.11,1048.62 34.49,1086.22 34.49,1096.38 ; -3.11,1442.32 34.49,1479.92 34.49,1490.08 ; -3.11,1836.02 34.49,1873.62 34.49,1883.78 ; 36.83,134.92 74.49,134.92 ; 36.83,528.62 74.49,528.62 ; 36.83,922.32 74.49,922.32 ; 36.83,1316.02 74.49,1316.02 ; 36.83,1709.72 74.49,1709.72 ; 36.83,2103.43 74.49,2103.43 ; 71.89,-84.72 71.89,-125.48 v1(78.89,-132.48) v1(106.89,-132.48) ; 71.89,308.98 71.89,268.22 v1(78.89,261.22) v1(106.89,261.22) ; 71.89,702.68 71.89,661.92 v1(78.89,654.92) v1(106.89,654.92) ; 71.89,1096.38 71.89,1055.62 v1(78.89,1048.62) v1(106.89,1048.62) ; 71.89,1490.08 71.89,1449.32 v1(78.89,1442.32) v1(106.89,1442.32) ; 71.89,1883.78 71.89,1843.02 v1(78.89,1836.02) v1(106.89,1836.02) ; 504.45,53.46 499.5,48.52 v1(480.85,48.52) 480.85,50.52 v1(498.85,68.52) 498.85,76.52 530.85,108.52 564.85,108.52 579.25,94.12 579.25,53.46 ; 504.45,167.46 504.45,205.12 ; 536.85,207.52 566.85,207.52 579.25,195.12 579.25,167.46 579.25,145.12 594.85,129.52 620.85,129.52 656.85,93.52 656.85,2.52 651.85,-2.48 631.85,-2.48 616.85,12.52 608.85,20.52 v1(608.85,24.52) ; 546.85,12.52 576.85,12.52 ; 629.61,165.12 670.85,123.87 670.85,112.52 699.85,83.52 755.46,83.52 811.46,27.52 816.85,27.52 826.85,17.52 ; 724.09,165.12 734.25,165.12 761.85,137.52 826.85,137.52 ; 724.09,202.52 764.85,202.52 v1(771.85,209.52) v1(771.85,237.52)
  other v1: -657.55,-137.48 -303.22,-137.48 44.89,-137.48 311.85,-82.48 -582.55,-72.48 -228.22,-72.48 119.89,-72.48 741.85,-47.48 771.85,-47.48 311.85,-42.48 -678.55,-39.48 -324.22,-39.48 23.89,-39.48 311.85,-2.48 491.85,-1.48 582.85,2.52 -764.55,6.52 -410.22,6.52 -62.11,6.52 491.85,22.52 -746.55,34.52 -392.22,34.52 -44.11,34.52 311.85,37.52 -830.55,56.52 -476.22,56.52 -128.11,56.52 632.85,68.52 547.85,77.52 451.85,82.52 604.85,86.52 -664.55,90.52 -310.22,90.52 37.89,90.52 -755.55,91.52 -401.22,91.52 -53.11,91.52 -689.55,101.52 -335.22,101.52 12.89,101.52 509.85,126.52 -706.55,129.52 -352.22,129.52 -4.11,129.52 537.85,143.52 -834.55,147.52 -810.55,147.52 -480.22,147.52 -456.22,147.52 -132.11,147.52 -108.11,147.52 451.85,152.52 678.85,154.52 548.85,168.52 776.85,175.52 311.85,177.52 311.85,217.52 806.85,217.52 836.85,217.52 451.85,232.52 711.85,250.52 806.85,252.52 836.85,252.52 -657.55,256.22 -303.22,256.22 44.89,256.22 311.85,257.52 451.85,272.52 806.85,287.52 836.85,287.52 311.85,297.52 451.85,312.52 -582.55,321.22 -228.22,321.22 119.89,321.22 311.85,337.52 -678.55,354.22 -324.22,354.22 23.89,354.22 -764.55,400.22 -410.22,400.22 -62.11,400.22 -746.55,428.22 -392.22,428.22 -44.11,428.22 -830.55,450.22 -476.22,450.22 -128.11,450.22 -664.55,484.22 -310.22,484.22 37.89,484.22 -755.55,485.22 -401.22,485.22 -53.11,485.22 -689.55,495.22 -335.22,495.22 12.89,495.22 -706.55,523.22 -352.22,523.22 -4.11,523.22 -834.55,541.22 -810.55,541.22 -480.22,541.22 -456.22,541.22 -132.11,541.22 -108.11,541.22 -657.55,649.92 -303.22,649.92 44.89,649.92 -582.55,714.92 -228.22,714.92 119.89,714.92 -678.55,747.92 -324.22,747.92 23.89,747.92 -764.55,793.92 -410.22,793.92 -62.11,793.92 -746.55,821.92 -392.22,821.92 -44.11,821.92 -830.55,843.92 -476.22,843.92 -128.11,843.92 -664.55,877.92 -310.22,877.92 37.89,877.92 -755.55,878.92 -401.22,878.92 -53.11,878.92 -689.55,888.92 -335.22,888.92 12.89,888.92 -706.55,916.92 -352.22,916.92 -4.11,916.92 -834.55,934.92 -810.55,934.92 -480.22,934.92 -456.22,934.92 -132.11,934.92 -108.11,934.92 -657.55,1043.62 -303.22,1043.62 44.89,1043.62 -582.55,1108.62 -228.22,1108.62 119.89,1108.62 -678.55,1141.62 -324.22,1141.62 23.89,1141.62 -764.55,1187.62 -410.22,1187.62 -62.11,1187.62 -746.55,1215.62 -392.22,1215.62 -44.11,1215.62 -830.55,1237.62 -476.22,1237.62 -128.11,1237.62 -664.55,1271.62 -310.22,1271.62 37.89,1271.62 -755.55,1272.62 -401.22,1272.62 -53.11,1272.62 -689.55,1282.62 -335.22,1282.62 12.89,1282.62 -706.55,1310.62 -352.22,1310.62 -4.11,1310.62 -834.55,1328.62 -810.55,1328.62 -480.22,1328.62 -456.22,1328.62 -132.11,1328.62 -108.11,1328.62 -657.55,1437.32 -303.22,1437.32 44.89,1437.32 -582.55,1502.32 -228.22,1502.32 119.89,1502.32 -678.55,1535.32 -324.22,1535.32 23.89,1535.32 -764.55,1581.32 -410.22,1581.32 -62.11,1581.32 -746.55,1609.32 -392.22,1609.32 -44.11,1609.32 -830.55,1631.32 -476.22,1631.32 -128.11,1631.32 -664.55,1665.32 -310.22,1665.32 37.89,1665.32 -755.55,1666.32 -401.22,1666.32 -53.11,1666.32 -689.55,1676.32 -335.22,1676.32 12.89,1676.32 -706.55,1704.32 -352.22,1704.32 -4.11,1704.32 -834.55,1722.32 -810.55,1722.32 -480.22,1722.32 -456.22,1722.32 -132.11,1722.32 -108.11,1722.32 -657.55,1831.02 -303.22,1831.02 44.89,1831.02 -582.55,1896.02 -228.22,1896.02 119.89,1896.02 -678.55,1929.02 -324.22,1929.02 23.89,1929.02 -764.55,1975.02 -410.22,1975.02 -62.11,1975.02 -746.55,2003.02 -392.22,2003.02 -44.11,2003.02 -830.55,2025.02 -476.22,2025.02 -128.11,2025.02 -664.55,2059.02 -310.22,2059.02 37.89,2059.02 -755.55,2060.02 -401.22,2060.02 -53.11,2060.02 -689.55,2070.02 -335.22,2070.02 12.89,2070.02 -706.55,2098.02 -352.22,2098.02 -4.11,2098.02 -834.55,2116.02 -810.55,2116.02 -480.22,2116.02 -456.22,2116.02 -132.11,2116.02 -108.11,2116.02

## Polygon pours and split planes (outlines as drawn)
no net on Top1 "NONET_L01_P036" (solid, remove dead copper, pour order 36): -865.55,2186.02 -545.55,2186.02 -545.55,1786.02 -865.55,1786.02
no net on Top1 "NONET_L01_P034" (solid, remove dead copper, pour order 34): -865.55,1792.32 -545.55,1792.32 -545.55,1392.32 -865.55,1392.32
no net on Top1 "NONET_L01_P032" (solid, remove dead copper, pour order 32): -865.55,1398.62 -545.55,1398.62 -545.55,998.62 -865.55,998.62
no net on Top1 "NONET_L01_P030" (solid, remove dead copper, pour order 30): -865.55,1004.92 -545.55,1004.92 -545.55,604.92 -865.55,604.92
no net on Top1 "NONET_L01_P028" (solid, remove dead copper, pour order 28): -865.55,611.22 -545.55,611.22 -545.55,211.22 -865.55,211.22
no net on Top1 "NONET_L01_P026" (solid, remove dead copper, pour order 26): -865.55,217.52 -545.55,217.52 -545.55,-182.48 -865.55,-182.48
no net on Top1 "NONET_L01_P024" (solid, remove dead copper, pour order 24): -511.22,2186.02 -191.22,2186.02 -191.22,1786.02 -511.22,1786.02
no net on Top1 "NONET_L01_P022" (solid, remove dead copper, pour order 22): -511.22,1792.32 -191.22,1792.32 -191.22,1392.32 -511.22,1392.32
no net on Top1 "NONET_L01_P020" (solid, remove dead copper, pour order 20): -511.22,1398.62 -191.22,1398.62 -191.22,998.62 -511.22,998.62
no net on Top1 "NONET_L01_P018" (solid, remove dead copper, pour order 18): -511.22,1004.92 -191.22,1004.92 -191.22,604.92 -511.22,604.92
no net on Top1 "NONET_L01_P016" (solid, remove dead copper, pour order 16): -511.22,611.22 -191.22,611.22 -191.22,211.22 -511.22,211.22
no net on Top1 "NONET_L01_P014" (solid, remove dead copper, pour order 14): -511.22,217.52 -191.22,217.52 -191.22,-182.48 -511.22,-182.48
no net on Top1 "NONET_L01_P012" (solid, remove dead copper, pour order 12): -163.11,2186.02 156.89,2186.02 156.89,1786.02 -163.11,1786.02
no net on Top1 "NONET_L01_P010" (solid, remove dead copper, pour order 10): -163.11,1792.32 156.89,1792.32 156.89,1392.32 -163.11,1392.32
no net on Top1 "NONET_L01_P008" (solid, remove dead copper, pour order 8): -163.11,1398.62 156.89,1398.62 156.89,998.62 -163.11,998.62
no net on Top1 "NONET_L01_P006" (solid, remove dead copper, pour order 6): -163.11,1004.92 156.89,1004.92 156.89,604.92 -163.11,604.92
no net on Top1 "NONET_L01_P004" (solid, remove dead copper, pour order 4): -163.11,611.22 156.89,611.22 156.89,211.22 -163.11,211.22
no net on Top1 "NONET_L01_P003" (solid, remove dead copper, pour order 3): 196.85,-157.48 196.85,412.52 861.85,412.52 861.85,-157.48
no net on Top1 "NONET_L01_P000" (solid, remove dead copper, pour order 0): -163.11,217.52 156.89,217.52 156.89,-182.48 -163.11,-182.48
no net on Bottom2 "NONET_L02_P037" (solid, remove dead copper, pour order 37): -865.55,2186.02 -545.55,2186.02 -545.55,1786.02 -865.55,1786.02
no net on Bottom2 "NONET_L02_P035" (solid, remove dead copper, pour order 35): -865.55,1792.32 -545.55,1792.32 -545.55,1392.32 -865.55,1392.32
no net on Bottom2 "NONET_L02_P033" (solid, remove dead copper, pour order 33): -865.55,1398.62 -545.55,1398.62 -545.55,998.62 -865.55,998.62
no net on Bottom2 "NONET_L02_P031" (solid, remove dead copper, pour order 31): -865.55,1004.92 -545.55,1004.92 -545.55,604.92 -865.55,604.92
no net on Bottom2 "NONET_L02_P029" (solid, remove dead copper, pour order 29): -865.55,611.22 -545.55,611.22 -545.55,211.22 -865.55,211.22
no net on Bottom2 "NONET_L02_P027" (solid, remove dead copper, pour order 27): -865.55,217.52 -545.55,217.52 -545.55,-182.48 -865.55,-182.48
no net on Bottom2 "NONET_L02_P025" (solid, remove dead copper, pour order 25): -511.22,2186.02 -191.22,2186.02 -191.22,1786.02 -511.22,1786.02
no net on Bottom2 "NONET_L02_P023" (solid, remove dead copper, pour order 23): -511.22,1792.32 -191.22,1792.32 -191.22,1392.32 -511.22,1392.32
no net on Bottom2 "NONET_L02_P021" (solid, remove dead copper, pour order 21): -511.22,1398.62 -191.22,1398.62 -191.22,998.62 -511.22,998.62
no net on Bottom2 "NONET_L02_P019" (solid, remove dead copper, pour order 19): -511.22,1004.92 -191.22,1004.92 -191.22,604.92 -511.22,604.92
no net on Bottom2 "NONET_L02_P017" (solid, remove dead copper, pour order 17): -511.22,611.22 -191.22,611.22 -191.22,211.22 -511.22,211.22
no net on Bottom2 "NONET_L02_P015" (solid, remove dead copper, pour order 15): -511.22,217.52 -191.22,217.52 -191.22,-182.48 -511.22,-182.48
no net on Bottom2 "NONET_L02_P013" (solid, remove dead copper, pour order 13): -163.11,2186.02 156.89,2186.02 156.89,1786.02 -163.11,1786.02
no net on Bottom2 "NONET_L02_P011" (solid, remove dead copper, pour order 11): -163.11,1792.32 156.89,1792.32 156.89,1392.32 -163.11,1392.32
no net on Bottom2 "NONET_L02_P009" (solid, remove dead copper, pour order 9): -163.11,1398.62 156.89,1398.62 156.89,998.62 -163.11,998.62
no net on Bottom2 "NONET_L02_P007" (solid, remove dead copper, pour order 7): -163.11,1004.92 156.89,1004.92 156.89,604.92 -163.11,604.92
no net on Bottom2 "NONET_L02_P005" (solid, remove dead copper, pour order 5): -163.11,611.22 156.89,611.22 156.89,211.22 -163.11,211.22
no net on Bottom2 "NONET_L02_P002" (solid, remove dead copper, pour order 2): 196.85,-157.48 196.85,412.52 861.85,412.52 861.85,-157.48
no net on Bottom2 "NONET_L02_P001" (solid, remove dead copper, pour order 1): -163.11,217.52 156.89,217.52 156.89,-182.48 -163.11,-182.48

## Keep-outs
Keep-Out Layer:
  lines w5: -855.55,-122.48 ccw(c-820.55,-122.48) -820.55,-157.48 -590.55,-157.48 ccw(c-590.55,-122.48) -555.55,-122.48 -555.55,162.52 ccw(c-590.55,162.52) -590.55,197.52 -820.55,197.52 ccw(c-820.55,162.52) -855.55,162.52 -855.55,-122.48 ; -855.55,271.22 ccw(c-820.55,271.22) -820.55,236.22 -590.55,236.22 ccw(c-590.55,271.22) -555.55,271.22 -555.55,556.22 ccw(c-590.55,556.22) -590.55,591.22 -820.55,591.22 ccw(c-820.55,556.22) -855.55,556.22 -855.55,271.22 ; -855.55,664.92 ccw(c-820.55,664.92) -820.55,629.92 -590.55,629.92 ccw(c-590.55,664.92) -555.55,664.92 -555.55,949.92 ccw(c-590.55,949.92) -590.55,984.92 -820.55,984.92 ccw(c-820.55,949.92) -855.55,949.92 -855.55,664.92 ; -855.55,1058.62 ccw(c-820.55,1058.62) -820.55,1023.62 -590.55,1023.62 ccw(c-590.55,1058.62) -555.55,1058.62 -555.55,1343.62 ccw(c-590.55,1343.62) -590.55,1378.62 -820.55,1378.62 ccw(c-820.55,1343.62) -855.55,1343.62 -855.55,1058.62 ; -855.55,1452.32 ccw(c-820.55,1452.32) -820.55,1417.32 -590.55,1417.32 ccw(c-590.55,1452.32) -555.55,1452.32 -555.55,1737.32 ccw(c-590.55,1737.32) -590.55,1772.32 -820.55,1772.32 ccw(c-820.55,1737.32) -855.55,1737.32 -855.55,1452.32 ; -855.55,1846.02 ccw(c-820.55,1846.02) -820.55,1811.02 -590.55,1811.02 ccw(c-590.55,1846.02) -555.55,1846.02 -555.55,2131.02 ccw(c-590.55,2131.02) -590.55,2166.02 -820.55,2166.02 ccw(c-820.55,2131.02) -855.55,2131.02 -855.55,1846.02 ; -501.22,-122.48 ccw(c-466.22,-122.48) -466.22,-157.48 -236.22,-157.48 ccw(c-236.22,-122.48) -201.22,-122.48 -201.22,162.52 ccw(c-236.22,162.52) -236.22,197.52 -466.22,197.52 ccw(c-466.22,162.52) -501.22,162.52 -501.22,-122.48 ; -501.22,271.22 ccw(c-466.22,271.22) -466.22,236.22 -236.22,236.22 ccw(c-236.22,271.22) -201.22,271.22 -201.22,556.22 ccw(c-236.22,556.22) -236.22,591.22 -466.22,591.22 ccw(c-466.22,556.22) -501.22,556.22 -501.22,271.22 ; -501.22,664.92 ccw(c-466.22,664.92) -466.22,629.92 -236.22,629.92 ccw(c-236.22,664.92) -201.22,664.92 -201.22,949.92 ccw(c-236.22,949.92) -236.22,984.92 -466.22,984.92 ccw(c-466.22,949.92) -501.22,949.92 -501.22,664.92 ; -501.22,1058.62 ccw(c-466.22,1058.62) -466.22,1023.62 -236.22,1023.62 ccw(c-236.22,1058.62) -201.22,1058.62 -201.22,1343.62 ccw(c-236.22,1343.62) -236.22,1378.62 -466.22,1378.62 ccw(c-466.22,1343.62) -501.22,1343.62 -501.22,1058.62 ; -501.22,1452.32 ccw(c-466.22,1452.32) -466.22,1417.32 -236.22,1417.32 ccw(c-236.22,1452.32) -201.22,1452.32 -201.22,1737.32 ccw(c-236.22,1737.32) -236.22,1772.32 -466.22,1772.32 ccw(c-466.22,1737.32) -501.22,1737.32 -501.22,1452.32 ; -501.22,1846.02 ccw(c-466.22,1846.02) -466.22,1811.02 -236.22,1811.02 ccw(c-236.22,1846.02) -201.22,1846.02 -201.22,2131.02 ccw(c-236.22,2131.02) -236.22,2166.02 -466.22,2166.02 ccw(c-466.22,2131.02) -501.22,2131.02 -501.22,1846.02 ; -153.11,-122.48 ccw(c-118.11,-122.48) -118.11,-157.48 111.89,-157.48 ccw(c111.89,-122.48) 146.89,-122.48 146.89,162.52 ccw(c111.89,162.52) 111.89,197.52 -118.11,197.52 ccw(c-118.11,162.52) -153.11,162.52 -153.11,-122.48 ; -153.11,271.22 ccw(c-118.11,271.22) -118.11,236.22 111.89,236.22 ccw(c111.89,271.22) 146.89,271.22 146.89,556.22 ccw(c111.89,556.22) 111.89,591.22 -118.11,591.22 ccw(c-118.11,556.22) -153.11,556.22 -153.11,271.22 ; -153.11,664.92 ccw(c-118.11,664.92) -118.11,629.92 111.89,629.92 ccw(c111.89,664.92) 146.89,664.92 146.89,949.92 ccw(c111.89,949.92) 111.89,984.92 -118.11,984.92 ccw(c-118.11,949.92) -153.11,949.92 -153.11,664.92 ; -153.11,1058.62 ccw(c-118.11,1058.62) -118.11,1023.62 111.89,1023.62 ccw(c111.89,1058.62) 146.89,1058.62 146.89,1343.62 ccw(c111.89,1343.62) 111.89,1378.62 -118.11,1378.62 ccw(c-118.11,1343.62) -153.11,1343.62 -153.11,1058.62 ; -153.11,1452.32 ccw(c-118.11,1452.32) -118.11,1417.32 111.89,1417.32 ccw(c111.89,1452.32) 146.89,1452.32 146.89,1737.32 ccw(c111.89,1737.32) 111.89,1772.32 -118.11,1772.32 ccw(c-118.11,1737.32) -153.11,1737.32 -153.11,1452.32 ; -153.11,1846.02 ccw(c-118.11,1846.02) -118.11,1811.02 111.89,1811.02 ccw(c111.89,1846.02) 146.89,1846.02 146.89,2131.02 ccw(c111.89,2131.02) 111.89,2166.02 -118.11,2166.02 ccw(c-118.11,2131.02) -153.11,2131.02 -153.11,1846.02
  lines w10: 146.89,413.72 146.89,2131.02 ccw(c111.89,2131.02) 111.89,2166.02 -820.55,2166.02 ccw(c-820.55,2131.02) -855.55,2131.02 -855.55,-122.48 ccw(c-820.55,-122.48) -820.55,-157.48 196.85,-157.48 ; 148.09,412.52 196.85,412.52 ; 196.85,-157.48 196.85,127.52 196.85,412.52 ; 196.85,-157.48 421.85,-157.48 496.85,-82.48 811.85,-82.48 ccw(c811.85,-32.48) 861.85,-32.48 861.85,127.52 861.85,287.52 ccw(c811.85,287.52) 811.85,337.52 496.85,337.52 421.85,412.52 196.85,412.52

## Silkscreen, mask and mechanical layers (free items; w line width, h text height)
Top Overlay:
  drawing of 154 lines, arcs and shapes, not listed
  text "A V G" at -689.76,1795.69 h40
  text "A V G" at -335.43,1795.69 h40
  text "A V G" at 12.68,1795.69 h40
  text "A V G" at -689.76,1401.99 h40
  text "A V G" at -335.43,1401.99 h40
  text "A V G" at 12.68,1401.99 h40
  text "A V G" at -689.76,1008.29 h40
  text "A V G" at -335.43,1008.29 h40
  text "A V G" at 12.68,1008.29 h40
  text "A V G" at -689.76,614.59 h40
  text "A V G" at -335.43,614.59 h40
  text "A V G" at 12.68,614.59 h40
  text "A V G" at -689.76,220.89 h40
  text "A V G" at -335.43,220.89 h40
  text "A V G" at 12.68,220.89 h40
  text "A   V   G" at 818.18,-34.53 h40 r90
  text "G V C D" at 472.75,-106.66 h40 r90
  text "A V G" at -689.76,-172.81 h40
  text "A V G" at -335.43,-172.81 h40
  text "A V G" at 12.68,-172.81 h40
Bottom Overlay:
  text "D C V G" at -685.19,2124.02 h40
  text "D C V G" at -330.86,2124.02 h40
  text "D C V G" at 17.25,2124.02 h40
  text "D C V G" at -685.19,1730.32 h40
  text "D C V G" at -330.86,1730.32 h40
  text "D C V G" at 17.25,1730.32 h40
  text "D C V G" at -685.19,1336.62 h40
  text "D C V G" at -330.86,1336.62 h40
  text "D C V G" at 17.25,1336.62 h40
  text "D C V G" at -685.19,942.91 h40
  text "D C V G" at -330.86,942.91 h40
  text "D C V G" at 17.25,942.91 h40
  text "D C V G" at -685.19,549.21 h40
  text "D C V G" at -330.86,549.21 h40
  text "D C V G" at 17.25,549.21 h40
  text "D C V G" at -685.19,155.51 h40
  text "D C V G" at -330.86,155.51 h40
  text "D C V G" at 17.25,155.51 h40
Mechanical 1:
  lines w10: 196.85,-157.48 196.85,127.52 196.85,412.52 421.85,412.52 496.85,337.52 811.85,337.52 cw(c811.85,287.52) 861.85,287.52 861.85,127.52 861.85,-32.48 cw(c811.85,-32.48) 811.85,-82.48 496.85,-82.48 421.85,-157.48 196.85,-157.48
